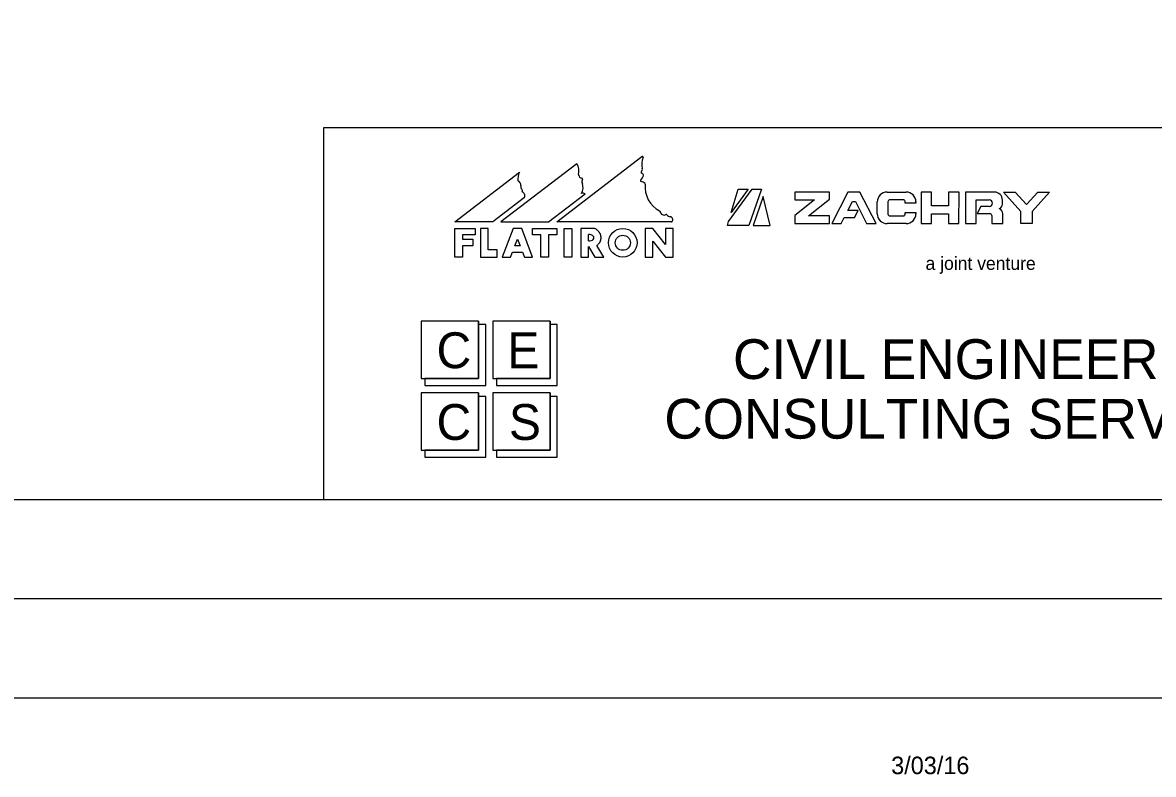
# Model space of a CAD drawing. Extents: x -2251 to 10196, y -13470 to 1199.
# Drawn here: x 3738 to 4022.4, y 30.2 to 219.3 of the extents above; entities that cross this region are included whole.
import ezdxf

# ---------------------------------------------------------------- set-up
doc = ezdxf.new("R2010")
doc.units = 0
for name, color, linetype in [('Level 3', 7, 'Continuous'), ('RD_SHT_Bndy', 7, 'Continuous'), ('RD_SHT_Iplotshp', 7, 'Continuous'), ('RD_SHT_Logo', 7, 'Continuous'), ('RD_SHT_Misc1', 7, 'Continuous'), ('RD_SHT_Snap', 7, 'Continuous'), ('RD_SHT_TX', 7, 'Continuous')]:
    doc.layers.add(name, color=color, linetype=linetype)

msp = doc.modelspace()

# ---------------------------------------------------------------- linework, layer by layer
at = {"layer": 'Level 3'}
msp.add_line((3965.07, 136.01), (3965.07, 136.01), dxfattribs=at)
msp.add_line((3965.07, 136.01), (3965.07, 136.01), dxfattribs=at)
msp.add_line((3965.07, 136.01), (3965.07, 136.01), dxfattribs=at)
msp.add_line((3965.07, 136.01), (3965.07, 136.01), dxfattribs=at)
at = {"layer": 'RD_SHT_Bndy'}
for p, q in [((2603.1, 99.35), (4278.1, 99.35)), ((4291.65, 74.35), (2531.65, 74.35)), ((4291.6, 49.3), (2531.6, 49.35))]:
    msp.add_line(p, q, dxfattribs=at)
at = {"layer": 'RD_SHT_Iplotshp'}
msp.add_lwpolyline([(2496.65, 1174.35), (4296.65, 1174.35), (4296.65, 74.35), (2496.65, 74.35)], close=True, dxfattribs=at)
at = {"layer": 'RD_SHT_Logo'}
for p, q in [((3872.32, 169.14), (3893.74, 185.56)), ((3877.35, 183.73), (3858.31, 169.14)), ((3846.7, 169.14), (3862.98, 181.62)), ((3915.56, 169.23), (3921.47, 177.41)), ((3920.48, 177.41), (3916.24, 171.53)), ((3916.24, 171.53), (3917.96, 177.41)), ((3917.96, 177.41), (3920.48, 177.41)), ((3923.82, 177.41), (3920.68, 168.24)), ((3921.47, 177.41), (3923.82, 177.41)), ((3940.93, 176.65), (3932.22, 176.65)), ((3932.22, 176.65), (3932.22, 174.7)), ((3940.93, 174.84), (3940.93, 176.65)), ((3945.58, 176.65), (3941.53, 168.7)), ((3948.58, 176.65), (3945.58, 176.65)), ((3952.63, 168.7), (3948.58, 176.65)), ((3955.44, 176.65), (3960.18, 176.65)), ((3966.62, 176.65), (3964.02, 176.65)), ((3964.02, 176.65), (3964.02, 168.7)), ((3966.62, 173.2), (3966.62, 176.65)), ((3970.9, 176.65), (3970.9, 173.2)), ((3973.51, 176.65), (3970.9, 176.65)), ((3973.5, 168.7), (3973.51, 176.65)), ((3982.43, 176.65), (3975.13, 176.65)), ((3975.13, 176.65), (3975.13, 168.7)), ((3984.68, 176.65), (3987.64, 176.65)), ((3989.08, 171.76), (3984.68, 176.65)), ((3987.64, 176.65), (3990.48, 173.49)), ((3990.48, 173.49), (3993.32, 176.65)), ((3996.28, 176.65), (3991.88, 171.76)), ((3993.32, 176.65), (3996.28, 176.65)), ((3864.27, 175.26), (3856.29, 169.14)), ((3870.3, 169.14), (3879.48, 176.18)), ((3924.24, 175.56), (3921.74, 168.24)), ((3925.99, 168.24), (3924.24, 175.56)), ((3937.2, 174.7), (3932.22, 170.76)), ((3932.22, 174.7), (3937.2, 174.7)), ((3935.63, 170.65), (3940.93, 174.84)), ((3945.57, 172.01), (3946.71, 174.25)), ((3946.71, 174.25), (3947.44, 174.25)), ((3947.44, 174.25), (3950.27, 168.7)), ((3952.94, 171.2), (3952.94, 174.15)), ((3955.64, 174.2), (3955.64, 171.15)), ((3959.48, 174.7), (3956.14, 174.7)), ((3959.98, 173.85), (3959.98, 174.2)), ((3962.68, 173.85), (3959.98, 173.85)), ((3962.68, 174.15), (3962.68, 173.85)), ((3977.83, 168.7), (3977.83, 174.69)), ((3977.83, 174.69), (3981.07, 174.69)), ((3984.43, 173.64), (3984.43, 174.65)), ((3932.22, 170.76), (3932.22, 168.7)), ((3940.93, 170.65), (3935.63, 170.65)), ((3940.93, 168.7), (3940.93, 170.65)), ((3948.15, 172.01), (3945.57, 172.01)), ((3947.23, 170.21), (3948.15, 172.01)), ((3956.14, 170.65), (3959.48, 170.65)), ((3959.98, 171.5), (3962.68, 171.5)), ((3959.98, 171.15), (3959.98, 171.5)), ((3962.68, 171.5), (3962.68, 171.2)), ((3970.9, 173.2), (3966.62, 173.2)), ((3966.62, 168.7), (3966.62, 171.2)), ((3966.62, 171.2), (3970.9, 171.2)), ((3970.9, 171.2), (3970.9, 168.7)), ((3979.03, 173.03), (3978.11, 171.23)), ((3978.11, 171.23), (3981.24, 171.23)), ((3981.07, 173.03), (3979.03, 173.03)), ((3981.74, 170.73), (3981.74, 168.7)), ((3983.68, 172.4), (3983.68, 172.53)), ((3984.54, 168.7), (3984.54, 171.24)), ((3989.08, 168.7), (3989.08, 171.76)), ((3991.88, 171.76), (3991.88, 168.7)), ((3856.29, 169.14), (3846.7, 169.14)), ((3858.31, 169.14), (3870.3, 169.14)), ((3901.19, 169.14), (3872.32, 169.14)), ((3915.27, 168.24), (3915.56, 169.23)), ((3920.68, 168.24), (3915.27, 168.24)), ((3921.74, 168.24), (3925.99, 168.24)), ((3932.22, 168.7), (3940.93, 168.7)), ((3941.53, 168.7), (3943.88, 168.7)), ((3943.88, 168.7), (3944.65, 170.21)), ((3944.65, 170.21), (3947.23, 170.21)), ((3950.27, 168.7), (3952.63, 168.7)), ((3960.18, 168.7), (3955.44, 168.7)), ((3964.02, 168.7), (3966.62, 168.7)), ((3970.9, 168.7), (3973.5, 168.7)), ((3975.13, 168.7), (3977.83, 168.7)), ((3981.74, 168.7), (3984.54, 168.7)), ((3991.88, 168.7), (3989.08, 168.7)), ((3846.72, 160.3), (3846.72, 167.5)), ((3846.72, 167.5), (3851.82, 167.5)), ((3851.82, 165.85), (3848.67, 165.85)), ((3848.67, 165.85), (3848.67, 164.79)), ((3851.82, 167.5), (3851.82, 165.85)), ((3855.12, 167.5), (3853.17, 167.5)), ((3853.17, 167.5), (3853.17, 160.3)), ((3855.12, 162.1), (3855.12, 167.5)), ((3861.42, 167.5), (3858.65, 160.29)), ((3863.52, 167.5), (3861.42, 167.5)), ((3866.28, 160.29), (3863.52, 167.5)), ((3866.22, 165.85), (3866.22, 167.5)), ((3866.22, 167.5), (3872.37, 167.5)), ((3868.32, 165.85), (3866.22, 165.85)), ((3868.32, 160.29), (3868.32, 165.85)), ((3872.37, 165.85), (3870.27, 165.85)), ((3870.27, 165.85), (3870.27, 160.29)), ((3872.37, 167.5), (3872.37, 165.85)), ((3874.17, 160.29), (3874.17, 167.5)), ((3874.17, 167.5), (3876.12, 167.5)), ((3876.12, 167.5), (3876.12, 160.29)), ((3881.8, 167.5), (3878.38, 167.5)), ((3878.38, 167.5), (3878.38, 160.29)), ((3880.33, 164.34), (3880.33, 165.99)), ((3896.52, 167.5), (3894.57, 167.5)), ((3894.57, 167.5), (3894.57, 160.29)), ((3899.67, 163.47), (3896.52, 167.5)), ((3901.62, 167.5), (3899.67, 167.5)), ((3899.67, 167.5), (3899.67, 163.47)), ((3901.62, 160.29), (3901.62, 167.5)), ((3848.67, 164.79), (3851.22, 164.79)), ((3851.22, 163.14), (3848.67, 163.14)), ((3848.67, 163.14), (3848.67, 160.3)), ((3851.22, 164.79), (3851.22, 163.14)), ((3861.83, 163.14), (3862.47, 164.8)), ((3863.1, 163.14), (3861.83, 163.14)), ((3862.47, 164.8), (3863.1, 163.14)), ((3880.33, 160.29), (3880.33, 162.98)), ((3880.33, 162.98), (3881.94, 160.29)), ((3884.16, 160.29), (3882.43, 163.18)), ((3896.52, 160.29), (3896.52, 164.33)), ((3896.52, 164.33), (3899.67, 160.29)), ((3848.67, 160.3), (3846.72, 160.3)), ((3853.17, 160.3), (3857.37, 160.29)), ((3857.37, 162.1), (3855.12, 162.1)), ((3857.37, 160.29), (3857.37, 162.1)), ((3858.65, 160.29), (3860.74, 160.29)), ((3860.74, 160.29), (3861.2, 161.49)), ((3861.2, 161.49), (3863.74, 161.49)), ((3863.74, 161.49), (3864.2, 160.29)), ((3864.2, 160.29), (3866.28, 160.29)), ((3870.27, 160.29), (3868.32, 160.29)), ((3876.12, 160.29), (3874.17, 160.29)), ((3878.38, 160.29), (3880.33, 160.29)), ((3881.94, 160.29), (3884.16, 160.29)), ((3894.57, 160.29), (3896.52, 160.29)), ((3899.67, 160.29), (3901.62, 160.29)), ((3852.67, 144.21), (3838.28, 144.21)), ((3838.28, 144.21), (3838.28, 129.77)), ((3852.67, 129.77), (3852.67, 144.21)), ((3852.67, 144.21), (3852.67, 129.77)), ((3854.48, 143.3), (3852.67, 143.3)), ((3854.48, 127.97), (3854.48, 143.3)), ((3870.67, 144.21), (3856.27, 144.21)), ((3856.27, 144.21), (3856.27, 129.77)), ((3870.67, 129.77), (3870.67, 144.21)), ((3870.67, 144.21), (3870.67, 129.77)), ((3872.48, 143.3), (3870.67, 143.3)), ((3872.48, 127.97), (3872.48, 143.3)), ((3838.28, 129.77), (3852.67, 129.77)), ((3852.67, 129.77), (3839.17, 129.77)), ((3839.17, 129.77), (3839.17, 127.97)), ((3856.27, 129.77), (3870.67, 129.77)), ((3870.67, 129.77), (3857.18, 129.77)), ((3857.18, 129.77), (3857.18, 127.97)), ((3852.67, 126.16), (3838.28, 126.16)), ((3838.28, 126.16), (3838.28, 111.73)), ((3839.17, 127.97), (3854.48, 127.97)), ((3852.67, 111.73), (3852.67, 126.16)), ((3852.67, 126.16), (3852.67, 111.73)), ((3854.48, 125.26), (3852.67, 125.26)), ((3854.48, 109.93), (3854.48, 125.26)), ((3870.67, 126.16), (3856.27, 126.16)), ((3856.27, 126.16), (3856.27, 111.73)), ((3857.18, 127.97), (3872.48, 127.97)), ((3870.67, 111.73), (3870.67, 126.16)), ((3870.67, 126.16), (3870.67, 111.73)), ((3872.48, 125.26), (3870.67, 125.26)), ((3872.48, 109.93), (3872.48, 125.26)), ((3838.28, 111.73), (3852.67, 111.73)), ((3852.67, 111.73), (3839.17, 111.73)), ((3839.17, 111.73), (3839.17, 109.93)), ((3856.27, 111.73), (3870.67, 111.73)), ((3870.67, 111.73), (3857.18, 111.73)), ((3857.18, 111.73), (3857.18, 109.93)), ((3839.17, 109.93), (3854.48, 109.93)), ((3857.18, 109.93), (3872.48, 109.93))]:
    msp.add_line(p, q, dxfattribs=at)
for radius in [3.6, 1.9]:
    msp.add_circle((3888.95, 163.9), radius, dxfattribs=at)
for centre, radius, start, end in [((3897.87, 183.66), 4.17, 156.4699, 195.3053), ((3893.86, 185.4), 0.2, 336.4699, 127.4657), ((3875.05, 181.98), 2.89, 342.0343, 37.2653), ((3893.13, 182.34), 0.749, 309.4079, 17.0499), ((3866.29, 179.88), 3.74, 152.2252, 185.8662), ((3862.1, 178.38), 1.21, 351.6466, 67.1294), ((3877.99, 181.03), 0.2, 162.0343, 220.8638), ((3876.86, 180.05), 1.3, 11.8745, 40.8638), ((3878.32, 180.36), 0.2, 191.8745, 279.8173), ((3878.44, 179.67), 0.499, 44.4799, 99.8173), ((3879.5, 179.28), 0.843, 144.641, 212.5499), ((3878.65, 179.88), 0.2, 324.641, 44.4799), ((3893.57, 179.5), 0.2, 133.0036, 262.3069), ((3891.59, 181.63), 2.7, 313.0036, 343.6807), ((3893.73, 181.61), 0.2, 129.4079, 246.863), ((3893.31, 177.56), 1.76, 45.283, 82.3069), ((3893.27, 180.53), 0.973, 20.4113, 66.863), ((3864.29, 178.06), 1, 171.6466, 221.9371), ((3863.11, 176.99), 0.592, 327.6019, 41.9371), ((3863.3, 175.67), 1.05, 337.4201, 73.1261), ((3875.8, 177.82), 3.16, 331.2486, 18.4584), ((3878.92, 175.56), 0.827, 48.0701, 115.7229), ((3894.4, 178.67), 0.2, 353.8329, 45.283), ((3901.36, 177.92), 6.8, 173.8329, 242.3928), ((3955.44, 174.15), 2.5, 89.9984, 179.9984), ((3960.18, 174.15), 2.5, 359.9984, 89.9984), ((3982.43, 174.65), 2, 359.9984, 89.9984), ((3956.14, 174.2), 0.5, 89.9984, 179.9984), ((3959.48, 174.2), 0.5, 359.9984, 89.9984), ((3981.07, 173.86), 0.831, 269.9984, 89.9984), ((3983.23, 173.64), 1.2, 291.95, 359.9984), ((3898.12, 171.72), 0.2, 9.0833, 62.3928), ((3899.35, 171.91), 1.04, 189.0833, 295.769), ((3899.89, 170.79), 0.2, 33.7112, 115.769), ((3900.89, 171.46), 1.01, 213.7112, 268.6299), ((3955.44, 171.2), 2.5, 179.9984, 269.9984), ((3956.14, 171.15), 0.5, 179.9984, 269.9984), ((3959.48, 171.15), 0.5, 269.9984, 359.9984), ((3960.18, 171.2), 2.5, 269.9984, 359.9984), ((3981.24, 170.73), 0.5, 359.9984, 89.9984), ((3983.34, 171.24), 1.2, 359.9984, 73.7977), ((3900.86, 170.26), 0.2, 78.9712, 88.6299), ((3900.75, 169.7), 0.767, 320.912, 78.9712), ((3901.19, 169.34), 0.2, 269.9984, 320.912)]:
    msp.add_arc(centre, radius, start, end, dxfattribs=at)
msp.add_ellipse((3880.33, 165.17), major_axis=(1.36, 0), ratio=0.609965, start_param=4.712389, end_param=7.853982, dxfattribs=at)
msp.add_open_spline([(3882.43, 163.18), (3882.51, 163.24), (3882.59, 163.3), (3882.81, 163.51), (3882.95, 163.66), (3883.13, 163.93), (3883.19, 164.03), (3883.29, 164.23), (3883.34, 164.34), (3883.41, 164.56), (3883.44, 164.68), (3883.47, 164.92), (3883.48, 165.04), (3883.48, 165.29), (3883.47, 165.41), (3883.44, 165.65), (3883.41, 165.77), (3883.34, 165.99), (3883.29, 166.1), (3883.19, 166.3), (3883.13, 166.4), (3882.95, 166.67), (3882.81, 166.82), (3882.52, 167.09), (3882.37, 167.2), (3882.08, 167.37), (3881.94, 167.44), (3881.8, 167.5)], degree=3, dxfattribs=at)
at = {"layer": 'RD_SHT_Misc1'}
msp.add_lwpolyline([(4296.65, 74.35), (4296.68, 1174.35), (2596.68, 1174.4), (2596.65, 74.4)], close=True, dxfattribs=at)
at = {"layer": 'RD_SHT_Snap'}
msp.add_lwpolyline([(2508.15, 1174.35), (4308.15, 1174.35), (4308.15, 74.35), (2508.15, 74.35)], close=True, dxfattribs=at)
at = {"layer": 'RD_SHT_TX'}
for p, q in [((3813.76, 99.35), (3813.76, 192.85)), ((3813.76, 99.35), (3813.76, 192.85)), ((3813.76, 192.85), (4278.1, 192.85))]:
    msp.add_line(p, q, dxfattribs=at)

# ---------------------------------------------------------------- texts
at = {"layer": 'RD_SHT_Logo'}
msp.add_text('a joint venture', height=3.3, rotation=359.9984, dxfattribs=at).set_placement((3965.08, 157.07))
for s, height, p in [('C', 9.02, (3842.11, 132.34)), ('E', 9.02, (3859.9, 132.34)), ('CIVIL ENGINEERING', 10, (3916.67, 129.62)), ('C', 9.02, (3842.11, 114.29)), ('S', 9.02, (3860.32, 114.29)), ('CONSULTING SERVICES, INC.', 10, (3899.39, 114.62))]:
    msp.add_text(s, height=height, dxfattribs=at).set_placement(p)
at = {"layer": 'RD_SHT_TX'}
msp.add_text('3/03/16', height=4.408, dxfattribs=at).set_placement((3956.45, 30.22))

doc.saveas('drawing.dxf')
